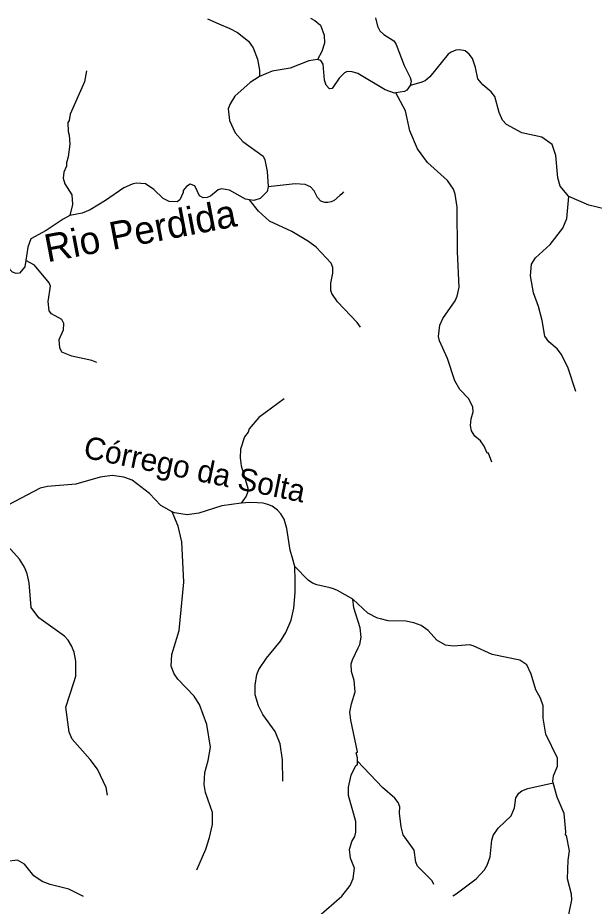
# Model space of a CAD drawing. Extents: x 280.4 to 335.6, y 8893.9 to 8949.5.
# Drawn here: x 288.88 to 293.02, y 8942.9 to 8949.29 of the extents above; entities that cross this region are included whole.
import ezdxf
from ezdxf.enums import TextEntityAlignment as Align

# ---------------------------------------------------------------- set-up
doc = ezdxf.new("R2010")
doc.units = 0
doc.header["$LTSCALE"] = 0.064
doc.layers.add('61', color=7, linetype='Continuous')
doc.layers.add('7', color=7, linetype='Continuous', lineweight=25)

msp = doc.modelspace()

# ---------------------------------------------------------------- linework, layer by layer
at = {"layer": '7'}
for points in [[(291.4492, 8949.294), (291.4648, 8949.2333), (291.4817, 8949.2011), (291.5098, 8949.1743), (291.582, 8949.1269), (291.5929, 8949.1146), (291.5987, 8949.1028), (291.6561, 8948.9516), (291.7007, 8948.8652), (291.7066, 8948.8383), (291.7004, 8948.8077)], [(290.2424, 8949.2873), (290.3231, 8949.2506), (290.402, 8949.2169), (290.4578, 8949.1875), (290.5042, 8949.1528), (290.5357, 8949.1246), (290.5693, 8949.0781), (290.6013, 8948.9974), (290.6164, 8948.9168), (290.6151, 8948.871)], [(290.9839, 8949.2914), (291.0148, 8949.2746), (291.0538, 8949.2405), (291.0805, 8949.1684), (291.0838, 8949.1117), (291.0633, 8949.0509), (291.0323, 8948.9928)], [(292.8422, 8948.008), (292.7789, 8948.0818), (292.7615, 8948.1417), (292.7467, 8948.3023), (292.7212, 8948.383), (292.6479, 8948.4343), (292.5024, 8948.4654), (292.3921, 8948.5256), (292.365, 8948.5575), (292.3399, 8948.6136), (292.3082, 8948.728), (292.2831, 8948.7606), (292.223, 8948.8114), (292.1861, 8948.8539), (292.1693, 8948.9365), (292.1489, 8948.9999), (292.1236, 8949.0327), (292.0955, 8949.0572), (292.0577, 8949.0628), (292.0282, 8949.0608), (291.9937, 8949.0469), (291.9728, 8949.0319), (291.8403, 8948.8684), (291.8069, 8948.8407), (291.7766, 8948.8274), (291.7004, 8948.8077)], [(291.0323, 8948.9928), (290.9706, 8948.9831), (290.8368, 8948.9316), (290.7067, 8948.9101), (290.6151, 8948.871)], [(291.5962, 8948.7537), (291.5861, 8948.7523), (291.5195, 8948.7748), (291.3244, 8948.8929), (291.2837, 8948.9062), (291.2474, 8948.9066), (291.2265, 8948.8971), (291.1882, 8948.8604), (291.1385, 8948.7856), (291.1203, 8948.7836), (291.0963, 8948.8091), (291.0842, 8948.8447), (291.074, 8948.9605), (291.0581, 8948.9862), (291.0323, 8948.9928)], [(289.3713, 8948.9118), (289.3565, 8948.8327), (289.2547, 8948.6011), (289.2478, 8948.554), (289.2381, 8948.54), (289.2396, 8948.4768), (289.2478, 8948.4506), (289.2526, 8948.3848), (289.2397, 8948.2945), (289.2274, 8948.2511), (289.2283, 8948.2275), (289.2093, 8948.1826), (289.2047, 8948.1392), (289.2161, 8948.0992), (289.2654, 8948.0209), (289.2717, 8947.9499), (289.2526, 8947.872)], [(290.6151, 8948.871), (290.5496, 8948.8294), (290.4381, 8948.7306), (290.4042, 8948.6759), (290.3915, 8948.6393), (290.401, 8948.5544), (290.4398, 8948.4674), (290.4964, 8948.405), (290.6413, 8948.2993), (290.6548, 8948.2732), (290.6713, 8948.189), (290.6785, 8948.0811), (290.6777, 8948.0771)], [(291.7004, 8948.8077), (291.6751, 8948.7735), (291.6584, 8948.7627), (291.5962, 8948.7537)], [(292.2867, 8946.0973), (292.2621, 8946.1613), (292.2544, 8946.1627), (292.2327, 8946.2118), (292.2064, 8946.2509), (292.1645, 8946.2856), (292.1411, 8946.3217), (292.133, 8946.3608), (292.1381, 8946.409), (292.1521, 8946.46), (292.1502, 8946.4951), (292.1188, 8946.5546), (292.0562, 8946.6193), (292.0201, 8946.6817), (291.9679, 8946.8438), (291.9097, 8946.9695), (291.9028, 8947.0023), (291.9122, 8947.0822), (291.9348, 8947.131), (292.0225, 8947.259), (292.0374, 8947.2925), (292.0529, 8947.3557), (292.0402, 8947.61), (292.0369, 8947.9306), (292.0242, 8948.0259), (292.0104, 8948.06), (291.9677, 8948.1231), (291.8237, 8948.2526), (291.7523, 8948.3501), (291.698, 8948.4808), (291.6656, 8948.6254), (291.5962, 8948.7537)], [(289.6996, 8948.097), (289.6406, 8948.0709), (289.5088, 8947.9794), (289.3981, 8947.9115), (289.3399, 8947.8889), (289.2526, 8947.872)], [(290.5434, 8947.9854), (290.516, 8947.99), (290.4, 8948.0534), (290.3433, 8948.0647), (290.319, 8948.0564), (290.2624, 8948.0111), (290.2401, 8948.0014), (290.2114, 8947.9996), (290.1833, 8948.0134), (290.1502, 8948.0848), (290.1179, 8948.097), (290.0913, 8948.0813), (290.0672, 8948.0506), (290.0664, 8948.0362), (290.0436, 8947.9849), (290.0228, 8947.9706), (289.9652, 8947.9725), (289.9219, 8947.9947), (289.8557, 8948.0597), (289.7953, 8948.0996), (289.7284, 8948.1033), (289.6996, 8948.097)], [(291.2194, 8948.0424), (291.2073, 8948.0284), (291.1931, 8948.0147), (291.1533, 8947.9803), (291.1308, 8947.9706), (291.1079, 8947.9644), (291.0859, 8947.9644), (291.0573, 8947.9749), (291.0332, 8948.0008), (291.0101, 8948.0489), (290.9838, 8948.0787), (290.9445, 8948.0944), (290.872, 8948.1), (290.6777, 8948.0771)], [(290.6777, 8948.0771), (290.6715, 8948.0452), (290.6201, 8947.9938), (290.5744, 8947.9802), (290.5434, 8947.9854)], [(291.3435, 8947.0675), (291.3182, 8947.1018), (291.1759, 8947.2514), (291.136, 8947.3111), (291.1286, 8947.3332), (291.1286, 8947.3861), (291.1445, 8947.4579), (291.1445, 8947.4978), (291.1314, 8947.5279), (291.0224, 8947.645), (290.9674, 8947.6856), (290.8477, 8947.756), (290.6877, 8947.8307), (290.6089, 8947.9018), (290.5434, 8947.9854)], [(292.8914, 8946.6058), (292.8371, 8946.7746), (292.7886, 8946.8719), (292.7566, 8946.9119), (292.698, 8946.9626), (292.6685, 8947.0037), (292.6497, 8947.1168), (292.6238, 8947.2173), (292.5868, 8947.3149), (292.5665, 8947.4366), (292.5737, 8947.5221), (292.6022, 8947.5661), (292.707, 8947.6635), (292.7985, 8947.7795), (292.8273, 8947.849), (292.8422, 8948.008)], [(293.7599, 8947.202), (293.7197, 8947.2591), (293.6947, 8947.3585), (293.6698, 8947.4252), (293.6085, 8947.5218), (293.4238, 8947.7225), (293.3325, 8947.8102), (293.2709, 8947.851), (293.1059, 8947.9175), (292.9845, 8947.9465), (292.8422, 8948.008)], [(289.2526, 8947.872), (289.2032, 8947.8458), (289.0822, 8947.7632), (288.9701, 8947.7035), (288.9488, 8947.6428), (288.9352, 8947.5489)], [(288.9352, 8947.5489), (288.9285, 8947.5027), (288.8892, 8947.4568), (288.8648, 8947.4542), (288.8402, 8947.4638), (288.8223, 8947.4809), (288.8189, 8947.4894)], [(289.4453, 8946.8151), (289.4088, 8946.8291), (289.2664, 8946.8594), (289.1937, 8946.8898), (289.1791, 8946.9208), (289.1743, 8946.9793), (289.2058, 8947.0493), (289.2077, 8947.0957), (289.1934, 8947.1225), (289.1207, 8947.1649), (289.1037, 8947.1868), (289.0962, 8947.2534), (289.112, 8947.3629), (289.103, 8947.3882), (288.9967, 8947.5148), (288.9352, 8947.5489)], [(290.793, 8946.5539), (290.6105, 8946.4177), (290.5426, 8946.3375), (290.5336, 8946.3131), (290.5088, 8946.2795), (290.4798, 8946.1902), (290.4761, 8946.1291), (290.485, 8946.072), (290.5318, 8945.9098), (290.5305, 8945.8788), (290.5199, 8945.8519), (290.4833, 8945.8027)], [(289.9881, 8945.741), (289.9064, 8945.7867), (289.8245, 8945.8712), (289.6995, 8945.9679), (289.6412, 8945.9891), (289.5549, 8946.0019), (289.4701, 8945.9895), (289.2958, 8945.9396), (289.09, 8945.9215), (289.0374, 8945.9109), (288.7591, 8945.7639), (288.6526, 8945.7196)], [(290.4833, 8945.8027), (290.3449, 8945.7828), (290.1794, 8945.7303), (290.0954, 8945.7174), (290.0044, 8945.7319), (289.9881, 8945.741)], [(290.8707, 8945.3471), (290.8525, 8945.4072), (290.8367, 8945.4647), (290.8119, 8945.6213), (290.7936, 8945.6879), (290.7703, 8945.7267), (290.7459, 8945.7512), (290.7078, 8945.7801), (290.677, 8945.7926), (290.6423, 8945.802), (290.6017, 8945.8054), (290.5464, 8945.8068), (290.4833, 8945.8027)], [(289.5233, 8943.702), (289.5131, 8943.7579), (289.4497, 8943.8903), (289.3987, 8943.9592), (289.2694, 8944.1061), (289.2457, 8944.1557), (289.224, 8944.3347), (289.281, 8944.5116), (289.2958, 8944.5577), (289.2942, 8944.6649), (289.2816, 8944.7314), (289.2639, 8944.7768), (289.2386, 8944.8177), (289.2126, 8944.8456), (289.0283, 8944.9776), (288.9745, 8945.0516), (288.9596, 8945.2293), (288.9455, 8945.295), (288.9248, 8945.343), (288.8884, 8945.4), (288.8045, 8945.4924), (288.7424, 8945.6245), (288.7142, 8945.6654), (288.6526, 8945.7196)], [(290.1644, 8943.164), (290.2309, 8943.3138), (290.2572, 8943.3965), (290.2777, 8943.4918), (290.2775, 8943.5772), (290.2265, 8943.7221), (290.2171, 8943.7782), (290.2235, 8943.8653), (290.2473, 8943.9517), (290.2633, 8944.0471), (290.2363, 8944.21), (290.1846, 8944.3554), (290.1543, 8944.4022), (290.1458, 8944.4153), (290.0279, 8944.5361), (290.0014, 8944.5748), (289.9806, 8944.6291), (289.9849, 8944.7145), (290.0375, 8944.8873), (290.0713, 8945.2335), (290.0568, 8945.5237), (290.03, 8945.6366), (289.9881, 8945.741)], [(290.7841, 8943.8021), (290.7824, 8943.9568), (290.7649, 8944.0721), (290.729, 8944.1589), (290.6409, 8944.2812), (290.6099, 8944.3449), (290.5852, 8944.4246), (290.5852, 8944.4314), (290.5851, 8944.4924), (290.597, 8944.5695), (290.6111, 8944.6051), (290.6669, 8944.6879), (290.7681, 8944.8103), (290.8052, 8944.8722), (290.8444, 8944.9608), (290.8632, 8945.0462), (290.8727, 8945.1608), (290.8727, 8945.247), (290.8707, 8945.3471)], [(291.2884, 8945.1128), (291.1777, 8945.1741), (291.1476, 8945.1856), (291.1243, 8945.1926), (291.0279, 8945.2148), (290.996, 8945.2276), (290.9659, 8945.249), (290.8707, 8945.3471)], [(291.3202, 8943.9458), (291.3203, 8943.9703), (291.3114, 8944.0064), (291.3201, 8944.0149), (291.2727, 8944.242), (291.2663, 8944.2995), (291.2775, 8944.3586), (291.3044, 8944.4443), (291.297, 8944.5279), (291.2786, 8944.5909), (291.276, 8944.6464), (291.2841, 8944.6752), (291.3265, 8944.7622), (291.3386, 8944.787), (291.3461, 8944.8378), (291.3396, 8944.9048), (291.295, 8945.0488), (291.2884, 8945.1128)], [(292.7294, 8943.7914), (292.7264, 8943.803), (292.7314, 8943.8416), (292.7596, 8943.9095), (292.7596, 8943.9683), (292.6765, 8944.1412), (292.6575, 8944.2548), (292.6569, 8944.3435), (292.6362, 8944.4001), (292.6037, 8944.4597), (292.5711, 8944.5722), (292.5385, 8944.6397), (292.4887, 8944.6729), (292.2897, 8944.713), (292.1537, 8944.7773), (292.1258, 8944.7831), (292.0106, 8944.7738), (291.9532, 8944.782), (291.8917, 8944.8169), (291.83, 8944.8877), (291.7795, 8944.9231), (291.7251, 8944.9428), (291.6675, 8944.9526), (291.5414, 8944.957), (291.4852, 8944.9702), (291.4651, 8944.975), (291.3944, 8945.011), (291.2884, 8945.1128)], [(289.3494, 8942.9724), (289.2446, 8943.0256), (289.109, 8943.0597), (289.0521, 8943.082), (288.9924, 8943.1212), (288.9259, 8943.2068), (288.874, 8943.2334), (288.7155, 8943.2161), (288.6512, 8943.2238), (288.6073, 8943.2361), (288.5401, 8943.2783), (288.4499, 8943.36), (288.398, 8943.4285), (288.3886, 8943.4505), (288.4006, 8943.5012), (288.4243, 8943.5374), (288.5133, 8943.6298), (288.5373, 8943.6681), (288.5631, 8943.7591), (288.5503, 8943.85), (288.5201, 8943.9197), (288.4649, 8943.9939), (288.4331, 8944.0105)], [(290.9613, 8942.7737), (291.0429, 8942.832), (291.2085, 8942.9745), (291.2689, 8943.0524), (291.2908, 8943.1029), (291.2997, 8943.1769), (291.2705, 8943.249), (291.2629, 8943.3121), (291.2808, 8943.37), (291.3013, 8943.4039), (291.3077, 8943.4349), (291.3077, 8943.5128), (291.2571, 8943.6995), (291.2566, 8943.759), (291.2758, 8943.8461), (291.3084, 8943.9147), (291.3201, 8943.9235), (291.3202, 8943.9458)], [(291.87, 8943.0598), (291.8587, 8943.086), (291.752, 8943.191), (291.7399, 8943.2213), (291.7295, 8943.306), (291.6496, 8943.4171), (291.6342, 8943.4738), (291.6229, 8943.5717), (291.6243, 8943.6184), (291.6143, 8943.6484), (291.59, 8943.6803), (291.5003, 8943.7574), (291.3202, 8943.9458)], [(292.0056, 8942.9783), (292.0315, 8942.9914), (292.175, 8943.1013), (292.2336, 8943.1649), (292.2531, 8943.1975), (292.2746, 8943.2586), (292.2865, 8943.3784), (292.2979, 8943.4117), (292.3321, 8943.4648), (292.4259, 8943.554), (292.4505, 8943.6098), (292.4593, 8943.6839), (292.4812, 8943.7162), (292.504, 8943.7341), (292.5473, 8943.7507), (292.7294, 8943.7914)], [(292.675, 8942.1621), (292.6856, 8942.2168), (292.6821, 8942.2327), (292.6931, 8942.2615), (292.7237, 8942.3074), (292.7726, 8942.3556), (292.905, 8942.4481), (292.9357, 8942.4931), (292.9469, 8942.5252), (292.9357, 8942.5827), (292.8699, 8942.7209), (292.843, 8942.8105), (292.8433, 8942.856), (292.8622, 8942.9493), (292.8604, 8942.989), (292.8304, 8943.1009), (292.8367, 8943.2345), (292.8461, 8943.3023), (292.824, 8943.4112), (292.8178, 8943.4152), (292.8205, 8943.4374), (292.8077, 8943.571), (292.7562, 8943.6877), (292.7294, 8943.7914)]]:
    msp.add_lwpolyline(points, dxfattribs=at)

# ---------------------------------------------------------------- texts
at = {"layer": '61'}
for s, height, rotation, p in [('Rio Perdida', 0.2, 10.784, (289.7763, 8947.665)), ('Córrego da Solta', 0.16, 348.41, (290.1343, 8945.9689))]:
    msp.add_text(s, height=height, rotation=rotation, dxfattribs=at).set_placement(p, align=Align.CENTER)

doc.saveas('drawing.dxf')
